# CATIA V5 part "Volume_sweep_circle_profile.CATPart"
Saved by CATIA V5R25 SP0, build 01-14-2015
Part number: Part1
Bounding box of the stored display mesh (mm): x -183.601 to 0, y -90.736 to 90.736, z -90.731 to 90.731
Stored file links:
  E:\cadcim\GSD_cat_v5-6r2014\Part_files\Volume_sweep_circle_profile.CATPart
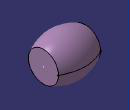
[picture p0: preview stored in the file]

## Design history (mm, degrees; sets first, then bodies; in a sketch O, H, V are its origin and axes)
Set1
  Sketch1 on xy-plane, origin (0, 0, 0), H (1, 0, 0), V (0, 1, 0)
    line L1 (0, 0) -> (-183.1008, 0)
    horizontal: L1 H
  Sketch2 on xy-plane, origin (0, 0, 0), H (1, 0, 0), V (0, 1, 0)
    spline S1 through (0, 65.5148) (-89.6654, 90.7245) (-183.6013, 65.5148)
    point P1 (0, 65.5148)
    coincidence: P1 V
  Sweep1: type Circle, Guide Sketch1, Reference Sketch2, Radius 55
Body1 (main body)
